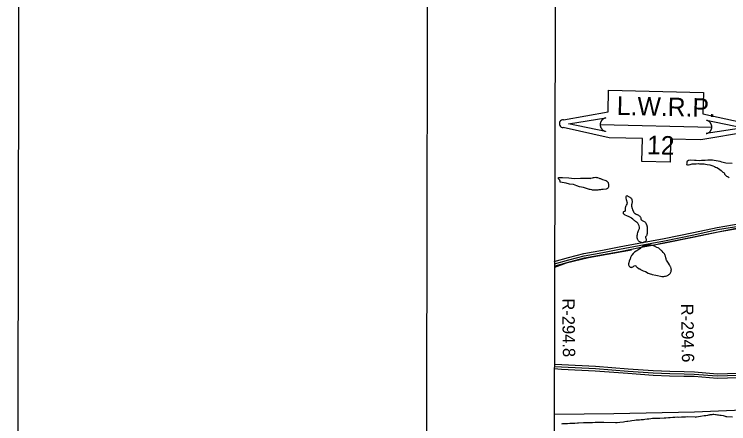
# Model space of a CAD drawing. Extents: x 3192986 to 3230865, y 867483 to 892886.
# Drawn here: x 3193570 to 3198376, y 880677 to 883432 of the extents above; entities that cross this region are included whole.
import ezdxf

# ---------------------------------------------------------------- set-up
doc = ezdxf.new("R2010")
doc.units = 0
for name, color, linetype in [('G-ANNO-NPLT', 7, 'Continuous'), ('V-ANNO-SYMB', 7, 'Continuous'), ('V-GRID-FRAM', 7, 'Continuous'), ('V-RIVR-RANG-IDEN', 7, 'Continuous'), ('V-ROAD-CNTR', 7, 'Continuous'), ('V-SITE-VEGE', 7, 'Continuous'), ('V-TOPO-SHOR', 7, 'Continuous'), ('V-TOPO-WATR-IDEN', 7, 'Continuous')]:
    doc.layers.add(name, color=color, linetype=linetype)

msp = doc.modelspace()

# ---------------------------------------------------------------- linework, layer by layer
at = {"layer": 'G-ANNO-NPLT'}
msp.add_lwpolyline([(3193569.6, 868136), (3230236.2, 868066.7), (3230281.9, 892233.3), (3193615.3, 892302.6)], close=True, dxfattribs=at)
at = {"layer": 'V-ANNO-SYMB'}
msp.add_lwpolyline([(3196320.9, 868755.9), (3229404.1, 868693.3), (3229447.4, 891609.8), (3196364.3, 891672.4), (3196320.9, 868755.9)], dxfattribs=at)
at = {"layer": 'V-GRID-FRAM'}
msp.add_lwpolyline([(3197186.7, 872920.9), (3197229, 891108.8)], dxfattribs=at)
at = {"layer": 'V-ROAD-CNTR'}
for points in [[(3197201.1, 881767.9), (3197297.4, 881794.4), (3197400.6, 881821.5), (3197527, 881844.1), (3197639.6, 881865.9), (3197770.6, 881891.1), (3197941.9, 881922.9), (3198139.7, 881963.1), (3198298.9, 881997.1), (3198452.7, 882023.6)], [(3197205.1, 881753.4), (3197301.3, 881779.9), (3197403.8, 881806.8), (3197529.8, 881829.4), (3197642.4, 881851.2), (3197773.4, 881876.4), (3197944.8, 881908.2), (3198142.7, 881948.4), (3198301.8, 881982.4), (3198456.9, 882009.1)], [(3197209.1, 881739), (3197305.2, 881765.5), (3197407, 881792.2), (3197532.5, 881814.6), (3197645.3, 881836.4), (3197776.2, 881861.7), (3197947.6, 881893.4), (3198145.8, 881933.7), (3198304.6, 881967.6), (3198461, 881994.6)], [(3198921.2, 881004.5), (3198905.7, 881010.4), (3198837.7, 881010.4), (3198724, 881007.7), (3198637.1, 881004.9), (3198571.8, 881015.2), (3198517.3, 881019.4), (3198456.9, 881015.6), (3198367.7, 881013.2), (3198298.5, 881010.8), (3198145.8, 881023.8), (3198076, 881025.1), (3197980, 881027.1), (3197868.7, 881032.1), (3197700.4, 881044), (3197480.4, 881060.6), (3197253.2, 881072), (3197204.4, 881075.1)], [(3198921.8, 880972.2), (3198900.2, 880980.4), (3198838, 880980.4), (3198724.8, 880977.7), (3198635.2, 880974.9), (3198568.3, 880985.3), (3198517.1, 880989.3), (3198458.2, 880985.7), (3198368.7, 880983.2), (3198297.7, 880980.8), (3198144.2, 880993.9), (3198075.4, 880995.1), (3197979, 880997.1), (3197867, 881002.2), (3197698.2, 881014.1), (3197478.5, 881030.6), (3197251.5, 881042), (3197202.5, 881045.2)], [(3198457.5, 881000.7), (3198368.2, 880998.2), (3198298.1, 880995.8), (3198145, 881008.8), (3198075.7, 881010.1), (3197979.5, 881012.1), (3197867.9, 881017.2), (3197699.3, 881029.1), (3197479.5, 881045.6), (3197252.4, 881057), (3197203.5, 881060.1)]]:
    msp.add_lwpolyline(points, dxfattribs=at)
at = {"layer": 'V-SITE-VEGE'}
for p, q in [((3198233, 880733.2), (3198236.6, 880734.9)), ((3198236.6, 880734.9), (3198241.9, 880737.1)), ((3198241.9, 880737.1), (3198246, 880737)), ((3198246, 880737), (3198252.5, 880738.1)), ((3198252.5, 880738.1), (3198257.2, 880738.6)), ((3198257.2, 880738.6), (3198266, 880739)), ((3198266, 880739), (3198270.8, 880740.1)), ((3198270.8, 880740.1), (3198276.6, 880740)), ((3198276.6, 880740), (3198286.6, 880738.6)), ((3198286.6, 880738.6), (3198292.5, 880737.9)), ((3198292.5, 880737.9), (3198301.3, 880737.1)), ((3198301.3, 880737.1), (3198308.3, 880735.8)), ((3198308.3, 880735.8), (3198317.1, 880733.9)), ((3197460.1, 880685.5), (3197477.2, 880686.4)), ((3197477.2, 880686.4), (3197489.5, 880686.1)), ((3197489.5, 880686.1), (3197507.2, 880686.4)), ((3197507.2, 880686.4), (3197519.5, 880686.1)), ((3197519.5, 880686.1), (3197537.2, 880687)), ((3197537.2, 880687), (3197615.3, 880685.4)), ((3197643, 880686), (3197669.5, 880688.5)), ((3197669.5, 880688.5), (3197678.4, 880690.6)), ((3197678.4, 880690.6), (3197691.3, 880692.7)), ((3197691.3, 880692.7), (3197698.4, 880694.4)), ((3197698.4, 880694.4), (3197712.6, 880696.4)), ((3197712.6, 880696.4), (3197724.4, 880698)), ((3197724.4, 880698), (3197742.1, 880701.1)), ((3197742.1, 880701.1), (3197753.8, 880702.7)), ((3197753.8, 880702.7), (3197776.2, 880703.4)), ((3197776.2, 880703.4), (3197788, 880704.3)), ((3197788, 880704.3), (3197793.8, 880704.2)), ((3197793.8, 880704.2), (3197802.1, 880705.8)), ((3197802.1, 880705.8), (3197810.9, 880706.2)), ((3197810.9, 880706.2), (3197828.1, 880709.4)), ((3197828.1, 880709.4), (3197838.1, 880709.8)), ((3197838.1, 880709.8), (3197853.4, 880711.3)), ((3197853.4, 880711.3), (3197862.8, 880712.9)), ((3197862.8, 880712.9), (3197876.3, 880713.2)), ((3197876.3, 880713.2), (3197885.2, 880714.2)), ((3197885.2, 880714.2), (3197896.3, 880714.5)), ((3197896.3, 880714.5), (3197912.8, 880714.2)), ((3197912.8, 880714.2), (3197941.6, 880715.4)), ((3197941.6, 880715.4), (3197952.8, 880717)), ((3197952.8, 880717), (3197971.1, 880717.8)), ((3197971.1, 880717.8), (3197982.9, 880719.3)), ((3197982.9, 880719.3), (3198001.1, 880720.1)), ((3198001.1, 880720.1), (3198012.9, 880721.6)), ((3198012.9, 880721.6), (3198031.1, 880721.9)), ((3198031.1, 880721.9), (3198041.7, 880721.7)), ((3198041.7, 880721.7), (3198057.6, 880723.1)), ((3198057.6, 880723.1), (3198067.6, 880722.9)), ((3198067.6, 880722.9), (3198081.1, 880723.2)), ((3198081.1, 880723.2), (3198085.2, 880723.2)), ((3198085.2, 880723.2), (3198096.4, 880724.1)), ((3198096.4, 880724.1), (3198150.5, 880723)), ((3198150.5, 880723), (3198154.6, 880721.8)), ((3198154.6, 880721.8), (3198158.7, 880722.9)), ((3198158.7, 880722.9), (3198174.1, 880726.1)), ((3198174.1, 880726.1), (3198187.6, 880728.2)), ((3198187.6, 880728.2), (3198210.6, 880731.3)), ((3198210.6, 880731.3), (3198222.4, 880731.6)), ((3198222.4, 880731.6), (3198233, 880733.2)), ((3198317.1, 880733.9), (3198325.3, 880733.1)), ((3198325.3, 880733.1), (3198338.2, 880731.1)), ((3198338.2, 880731.1), (3198345.2, 880729.2)), ((3198345.2, 880729.2), (3198353.4, 880727.3)), ((3198353.4, 880727.3), (3198358.1, 880726)), ((3198358.1, 880726), (3198363.4, 880724.7)), ((3198363.4, 880724.7), (3198401, 880724)), ((3197253.6, 880676.7), (3197260.1, 880677.1)), ((3197260.1, 880677.1), (3197269.5, 880678.1)), ((3197269.5, 880678.1), (3197285.4, 880677.8)), ((3197285.4, 880677.8), (3197291.9, 880678.3)), ((3197291.9, 880678.3), (3197306.6, 880679.8)), ((3197306.6, 880679.8), (3197316.6, 880680.1)), ((3197316.6, 880680.1), (3197330.7, 880681)), ((3197330.7, 880681), (3197340.7, 880680.8)), ((3197340.7, 880680.8), (3197358.9, 880681.7)), ((3197358.9, 880681.7), (3197366, 880681.5)), ((3197366, 880681.5), (3197400.1, 880683.8)), ((3197400.1, 880683.8), (3197414.3, 880684.1)), ((3197414.3, 880684.1), (3197426.6, 880685)), ((3197426.6, 880685), (3197434.3, 880685.5)), ((3197434.3, 880685.5), (3197448.4, 880685.8)), ((3197448.4, 880685.8), (3197460.1, 880685.5)), ((3197615.3, 880685.4), (3197625.9, 880685.8)), ((3197625.9, 880685.8), (3197643, 880686))]:
    msp.add_line(p, q, dxfattribs=at)
at = {"layer": 'V-TOPO-SHOR'}
for points in [[(3198398.5, 882428.2), (3198357.2, 882429.5), (3198347.6, 882431.5), (3198331.1, 882436.4), (3198318.9, 882440.3), (3198305.8, 882443.4), (3198277.9, 882448.6), (3198268.2, 882449.8), (3198252.4, 882450.3), (3198235.7, 882449.9), (3198217.2, 882448.7), (3198192.6, 882446.9), (3198177.6, 882446.4), (3198158.3, 882447), (3198146.9, 882448.3), (3198122.3, 882449), (3198104.7, 882446.9), (3198098.4, 882443.6), (3198094.8, 882441.1), (3198094.7, 882435.8), (3198093.6, 882428.8), (3198093.4, 882421.8), (3198098.6, 882419), (3198106.5, 882419.6), (3198117.1, 882421.1), (3198130.4, 882425), (3198135.7, 882425.8), (3198143.6, 882426.4), (3198156.8, 882426), (3198172.6, 882427.3), (3198180.5, 882426.1), (3198197.2, 882425.6), (3198210.3, 882424.3), (3198219.1, 882423.2), (3198230.4, 882420.2), (3198249.7, 882417.9), (3198268.8, 882412), (3198281, 882407.2)], [(3198281, 882407.2), (3198287, 882403.5), (3198295.7, 882400.6), (3198307.8, 882393.2), (3198316.4, 882387.7), (3198325, 882381.3), (3198337.8, 882370.3), (3198344.7, 882364), (3198347.2, 882359.5), (3198348.8, 882355.9), (3198353.1, 882351.4), (3198362.5, 882343.2), (3198367.7, 882340.4), (3198373.7, 882336.7), (3198379.8, 882333.9)], [(3197433.5, 882254.3), (3197398.9, 882266.5), (3197371.8, 882270.2), (3197354.2, 882278.2), (3197331.3, 882286.7), (3197305.9, 882289), (3197283.8, 882295.5), (3197255.8, 882299.9), (3197243.1, 882302.8), (3197242.4, 882309), (3197240.8, 882316.4), (3197230.5, 882324.9), (3197231.2, 882332.7), (3197258.2, 882333.5), (3197299.6, 882330.1), (3197337.6, 882326.9), (3197378.2, 882328.4), (3197410.7, 882328.7), (3197438.5, 882329.3)], [(3197438.5, 882329.3), (3197442.3, 882328.3), (3197445.8, 882327), (3197449.6, 882327.9), (3197460, 882331.9), (3197466.4, 882333.3), (3197471.4, 882334.1), (3197481.9, 882334.6), (3197486.6, 882334.2), (3197494.5, 882332.8), (3197504.3, 882329.9), (3197509.4, 882327.6), (3197513.1, 882326.3), (3197518.6, 882324), (3197526.6, 882320.9), (3197543.5, 882316.1), (3197549.2, 882313.7), (3197552.7, 882312), (3197555.2, 882310.3), (3197558.9, 882307.1), (3197561.5, 882303.8), (3197564.7, 882298.6), (3197565.8, 882295.4), (3197566.9, 882290.4), (3197567.4, 882286.8), (3197568.1, 882277.9), (3197566.8, 882270.2), (3197564.5, 882264.1), (3197561.4, 882259.7), (3197556.9, 882256.2), (3197551.7, 882254.4), (3197532.4, 882252.4), (3197528.1, 882252.6), (3197524.7, 882252.5), (3197519.9, 882252), (3197513.4, 882250.9), (3197502, 882249.4), (3197495.9, 882248.4), (3197487.3, 882247.7), (3197479.6, 882247.3), (3197465.2, 882248.2), (3197458.9, 882248.8), (3197455.1, 882249.3), (3197443.3, 882251.8), (3197440.2, 882252.1), (3197433.5, 882254.3)], [(3197759.9, 882030.5), (3197756.2, 882032.7), (3197749.3, 882037.4), (3197742.1, 882043.3), (3197738.4, 882046.7), (3197730.5, 882053.1), (3197722.8, 882058.9), (3197719.6, 882061.1), (3197712, 882065.4), (3197707.5, 882067.7), (3197690.9, 882074.5), (3197680.3, 882080), (3197674.5, 882083.6), (3197671.8, 882086), (3197669.4, 882089.2), (3197667.5, 882093.5), (3197667.5, 882097.4), (3197668.7, 882101.4), (3197670.9, 882104.6), (3197674.1, 882106.2), (3197677.1, 882106.5), (3197680.3, 882107.3), (3197681.6, 882110.6), (3197682, 882113.6), (3197682.5, 882127.2), (3197682.9, 882131.3), (3197683.4, 882135.3), (3197684.5, 882139.4), (3197685.9, 882142.9), (3197688, 882146.9), (3197692.6, 882154.2), (3197693.8, 882157.3), (3197694.4, 882160.3), (3197692.6, 882168.2), (3197689.9, 882178.8), (3197689.5, 882181.9), (3197686.3, 882199), (3197686.3, 882202.6), (3197687, 882206.6), (3197688.9, 882209.7), (3197691.5, 882211.5), (3197694.7, 882210.9), (3197698, 882208.7), (3197701.9, 882206.2), (3197707.3, 882202.2), (3197711.3, 882200.2), (3197716, 882197.4), (3197718.3, 882195.5), (3197721.2, 882191.4), (3197723.7, 882186.4), (3197725.6, 882181.4), (3197727.1, 882177.1), (3197727.3, 882172.5), (3197726.8, 882167.9), (3197726.2, 882164.9), (3197724.7, 882160.7), (3197723.7, 882156.8), (3197722.3, 882148.5), (3197723, 882138.9), (3197723.6, 882135.7), (3197724.6, 882131.4), (3197726.4, 882125.4), (3197729.8, 882115.8), (3197733, 882108), (3197735.7, 882102.2), (3197738.6, 882097.4), (3197742.1, 882093.6), (3197747.4, 882090), (3197752.8, 882087.2), (3197757.1, 882085.3), (3197761, 882083.9), (3197770, 882079.4), (3197774.4, 882076.5), (3197778.2, 882072.8), (3197780.6, 882069.3), (3197782.6, 882065.5), (3197784, 882061.8), (3197785.9, 882054.7), (3197788.4, 882049.6), (3197791.3, 882046), (3197793.6, 882043.8), (3197797.5, 882041.4), (3197802.6, 882039.3), (3197811, 882035.4), (3197813.8, 882032.9), (3197815.6, 882030.3), (3197817.8, 882025.9), (3197824.5, 882010.3), (3197825.5, 882007.3), (3197826.7, 882002.4), (3197827.4, 881996.4), (3197827.7, 881977.3), (3197828.1, 881970.2), (3197827.8, 881960.4), (3197827.3, 881955.4), (3197826.2, 881951), (3197824.9, 881945.5), (3197823.1, 881941.2), (3197818.2, 881936.3), (3197816.8, 881933.3), (3197817.5, 881928.1)], [(3197904.5, 881887.1), (3198428.1, 881993.5), (3198504.8, 882018.3), (3198581.6, 882049.4), (3198645.6, 882077.4), (3198702.9, 882070.5), (3198878.3, 882084.7), (3198907.1, 882097.2), (3198935.8, 882103.3), (3198986.8, 882106), (3199053.5, 882086.2), (3199025.5, 882214.7)], [(3197817.5, 881928.1), (3197818.6, 881925.2), (3197820.6, 881921.6), (3197821.8, 881918.4), (3197821.8, 881913.8), (3197820.8, 881908.9), (3197819, 881905), (3197816.3, 881902), (3197806.4, 881897.1), (3197801.8, 881895.4), (3197798.7, 881894.4), (3197793.9, 881894.4), (3197790.7, 881895), (3197786.9, 881896.1), (3197783.7, 881897.5), (3197778.5, 881900.3), (3197774.5, 881903.2), (3197771.9, 881905.4), (3197769.5, 881908), (3197767.3, 881910.8), (3197765.2, 881914.3), (3197763.4, 881917.5), (3197761.6, 881921.7), (3197760.6, 881927.5), (3197760.2, 881937.9), (3197760.8, 881943.1), (3197761.8, 881949.1), (3197762.5, 881954.8), (3197764.9, 881963.7), (3197767, 881970.2), (3197769.7, 881976.1), (3197772.4, 881980.7), (3197774.1, 881985.9), (3197775.6, 881991), (3197776.3, 881995.1), (3197776, 882000.1), (3197774.3, 882007.3), (3197772.3, 882013.7), (3197770.4, 882017.9), (3197768.1, 882021.9), (3197765.2, 882025.4), (3197763, 882027.7), (3197759.9, 882030.5)], [(3197722.4, 881844.3), (3197432, 881793), (3197281.8, 881756.2), (3197205.1, 881728.3)], [(3197837.3, 881879.2), (3197826.7, 881876.5), (3197823.4, 881876.6), (3197819.4, 881876.2), (3197816.1, 881875.5), (3197811.8, 881874.2), (3197801.9, 881872.4), (3197797.9, 881870.8), (3197793.4, 881867.9), (3197789.2, 881864.6), (3197786.1, 881861.9), (3197780.3, 881856.4), (3197771, 881849.5), (3197757.2, 881839.7), (3197754.1, 881837.3), (3197742.6, 881829.9), (3197739, 881826.8), (3197733.8, 881821.5), (3197725.5, 881811.8), (3197722.6, 881807.9), (3197717.7, 881799.3), (3197715.4, 881794.4), (3197714.5, 881791), (3197712.9, 881786), (3197706.6, 881769.3), (3197703.8, 881760), (3197702.4, 881752.5), (3197702.7, 881745.8), (3197703.8, 881741), (3197705.6, 881737.8), (3197710.1, 881732.6), (3197713.6, 881730.5), (3197719.6, 881728.9), (3197722.9, 881728.5), (3197727.1, 881729.1), (3197731.8, 881731.2), (3197736, 881734.9), (3197738.2, 881737.2), (3197741.3, 881739.8), (3197745.5, 881741.4), (3197750.9, 881738.6), (3197754.8, 881735.1), (3197758.5, 881731), (3197761.7, 881727.9), (3197764.6, 881725.4), (3197774.1, 881719.4), (3197777.6, 881717.7), (3197783.8, 881714.4), (3197801.7, 881705.9), (3197815.4, 881699.8), (3197835.4, 881690.1), (3197840.9, 881687.7), (3197847.7, 881685), (3197855.8, 881682.4), (3197861, 881681), (3197886.2, 881676.5), (3197898.1, 881674.1), (3197917.2, 881669.7), (3197927.4, 881668.3), (3197931.2, 881668.2), (3197936.8, 881668.1), (3197940.3, 881668.3), (3197947, 881669), (3197951.8, 881669.9), (3197960.4, 881672.1), (3197968.9, 881676.5), (3197973.9, 881679.6), (3197977.1, 881682.3), (3197981.9, 881687.7), (3197984.4, 881691.2), (3197988.5, 881699.9), (3197990.1, 881706.7), (3197990.4, 881713.7), (3197990.1, 881717), (3197989, 881721.8), (3197986.2, 881729.5), (3197985.1, 881732.3), (3197982.6, 881737.2), (3197980.5, 881740.8), (3197977.1, 881745.9), (3197970.7, 881756.6), (3197961.6, 881771.2), (3197958.7, 881777.3), (3197956.6, 881782), (3197955.5, 881785.2), (3197953.6, 881793.2), (3197951.8, 881803.5), (3197949.8, 881809.3), (3197946.4, 881815.2), (3197944, 881818.9), (3197935.2, 881829.8), (3197928.6, 881837.4), (3197924.4, 881841.8), (3197920.5, 881845.4), (3197913.9, 881851.1), (3197911.1, 881853.1), (3197905.3, 881856.8), (3197900.8, 881859.4), (3197893.8, 881863), (3197876.2, 881870.8), (3197871, 881872.9)], [(3197871, 881872.9), (3197860.7, 881876.4), (3197855.7, 881877.5), (3197849.1, 881878.3), (3197842.6, 881878.6), (3197837.3, 881879.2)], [(3200534.2, 880915), (3200285.3, 880882.4), (3200119.5, 880872.9), (3199682.9, 880861.2), (3199446.9, 880849.2), (3199329, 880845.6), (3199178.9, 880815.2), (3199064.1, 880800.4), (3198995.5, 880794.7), (3198740.4, 880778), (3198145.9, 880755.2), (3197602.5, 880742.9), (3197204.9, 880739.5)]]:
    msp.add_lwpolyline(points, dxfattribs=at)
at = {"layer": 'V-TOPO-WATR-IDEN'}
msp.add_line((3197511.6, 882689.8), (3198262.6, 882672.6), dxfattribs=at)
for points in [[(3197264.3, 882721.9), (3197565, 882775.8), (3197568.3, 882920.5), (3198206.6, 882905.9), (3198203.3, 882761.2), (3198511.1, 882693.5)], [(3198509.9, 882640.5), (3198188.8, 882587.1), (3197985.4, 882591.7), (3197981.9, 882436.4), (3197792.8, 882440.7), (3197796.4, 882596), (3197571.6, 882601.2), (3197263.1, 882668.9)]]:
    msp.add_lwpolyline(points, dxfattribs=at)
for points in [[(3197548.1, 882643.9), (3197299.3, 882694.6), (3197550.1, 882733.9), (3197545.7, 882732.9), (3197541.5, 882731.6), (3197539.8, 882731), (3197538.4, 882730.3), (3197536.7, 882729.5), (3197535, 882728.7), (3197533.7, 882727.9), (3197531.8, 882726.7), (3197529.9, 882725.3), (3197528.9, 882724.6), (3197527.6, 882723.5), (3197526, 882722), (3197524.7, 882720.8), (3197523.5, 882719.5), (3197522.7, 882718.5), (3197521.8, 882717.5), (3197520.8, 882716.2), (3197519.9, 882715), (3197519.1, 882713.8), (3197518.4, 882712.7), (3197517.5, 882711.1), (3197516.6, 882709.6), (3197516, 882708.3), (3197515.3, 882706.8), (3197514.8, 882705.5), (3197514.3, 882704.3), (3197514, 882703.4), (3197513.6, 882702), (3197513.1, 882700.5), (3197512.8, 882699), (3197512.5, 882697.6), (3197512.2, 882696.2), (3197512, 882694.7), (3197511.8, 882693.5), (3197511.7, 882691.7), (3197511.6, 882689.8), (3197511.6, 882689.1), (3197511.6, 882688.2), (3197511.6, 882687.1), (3197511.7, 882686), (3197511.7, 882685), (3197511.8, 882684), (3197512, 882682.8), (3197512.1, 882682), (3197512.3, 882680.8), (3197512.5, 882679.7), (3197512.7, 882678.9), (3197513.1, 882676.9), (3197513.4, 882675.9), (3197513.6, 882675.2), (3197514, 882674), (3197514.4, 882673), (3197514.8, 882671.9), (3197515.3, 882670.7), (3197515.8, 882669.5), (3197516.2, 882668.6), (3197516.6, 882667.9), (3197517.1, 882666.9), (3197517.6, 882666), (3197518.2, 882665), (3197518.9, 882663.9), (3197519.6, 882662.9), (3197520.5, 882661.6), (3197521.1, 882660.8), (3197521.9, 882659.8), (3197522.7, 882658.9), (3197523.3, 882658.1), (3197524, 882657.4), (3197525.1, 882656.2), (3197525.2, 882656.2), (3197525.8, 882655.5), (3197526.3, 882655.1), (3197527.1, 882654.4), (3197528.1, 882653.5), (3197528.9, 882652.9), (3197529.6, 882652.3), (3197530.5, 882651.6), (3197531.5, 882651), (3197532.2, 882650.5), (3197533, 882650), (3197534.3, 882649.2), (3197535, 882648.8), (3197535.6, 882648.4), (3197536.2, 882648.1), (3197536.9, 882647.8), (3197537.7, 882647.4), (3197538.6, 882647), (3197539.5, 882646.6), (3197540.4, 882646.2), (3197541.6, 882645.8), (3197542.3, 882645.5), (3197543.4, 882645.1), (3197544.7, 882644.7), (3197545.7, 882644.5), (3197546.5, 882644.3), (3197547.2, 882644.1), (3197547.7, 882644)], [(3198226.1, 882718.5), (3198475, 882667.8), (3198224.1, 882628.5), (3198228.6, 882629.5), (3198232.8, 882630.8), (3198234.4, 882631.4), (3198235.9, 882632.1), (3198237.6, 882632.9), (3198239.2, 882633.7), (3198240.5, 882634.5), (3198242.4, 882635.7), (3198244.3, 882637.1), (3198245.3, 882637.8), (3198246.6, 882638.9), (3198248.3, 882640.4), (3198249.5, 882641.6), (3198250.8, 882642.9), (3198251.6, 882643.9), (3198252.4, 882644.9), (3198253.4, 882646.2), (3198254.3, 882647.4), (3198255.2, 882648.6), (3198255.8, 882649.7), (3198256.8, 882651.3), (3198257.6, 882652.8), (3198258.2, 882654.1), (3198258.9, 882655.6), (3198259.4, 882656.9), (3198259.9, 882658.1), (3198260.2, 882659), (3198260.7, 882660.4), (3198261.1, 882661.9), (3198261.4, 882663.4), (3198261.8, 882664.8), (3198262, 882666.2), (3198262.2, 882667.7), (3198262.4, 882668.9), (3198262.5, 882670.7), (3198262.6, 882672.6), (3198262.6, 882673.3), (3198262.6, 882674.2), (3198262.6, 882675.3), (3198262.5, 882676.4), (3198262.5, 882677.4), (3198262.4, 882678.4), (3198262.2, 882679.6), (3198262.1, 882680.4), (3198261.9, 882681.6), (3198261.7, 882682.7), (3198261.6, 882683.5), (3198261.1, 882685.5), (3198260.8, 882686.5), (3198260.6, 882687.2), (3198260.2, 882688.4), (3198259.8, 882689.4), (3198259.4, 882690.5), (3198258.9, 882691.7), (3198258.4, 882692.9), (3198258, 882693.8), (3198257.6, 882694.5), (3198257.1, 882695.5), (3198256.6, 882696.4), (3198256, 882697.4), (3198255.3, 882698.5), (3198254.7, 882699.5), (3198253.8, 882700.8), (3198253.1, 882701.6), (3198252.3, 882702.6), (3198251.6, 882703.5), (3198250.9, 882704.3), (3198250.2, 882705), (3198249.1, 882706.2), (3198249.1, 882706.2), (3198248.4, 882706.9), (3198247.9, 882707.3), (3198247.1, 882708), (3198246.1, 882708.9), (3198245.3, 882709.5), (3198244.6, 882710.1), (3198243.7, 882710.8), (3198242.7, 882711.4), (3198242.1, 882711.9), (3198241.2, 882712.5), (3198239.9, 882713.2), (3198239.2, 882713.6), (3198238.6, 882714), (3198238, 882714.3), (3198237.4, 882714.6), (3198236.5, 882715), (3198235.6, 882715.4), (3198234.7, 882715.8), (3198233.8, 882716.2), (3198232.6, 882716.6), (3198231.9, 882716.9), (3198230.8, 882717.3), (3198229.5, 882717.7), (3198228.5, 882717.9), (3198227.7, 882718.1), (3198227, 882718.3), (3198226.5, 882718.4)]]:
    msp.add_lwpolyline(points, close=True, dxfattribs=at)
msp.add_arc((3197263.7, 882695.4), 26.5, 88.6951, 268.6951, dxfattribs=at)

# ---------------------------------------------------------------- texts
at = {"layer": 'V-RIVR-RANG-IDEN'}
for s, rotation, p in [('R-294.8', 270.7577, (3197255.7, 881519.2)), ('R-294.6', 270.9666, (3198055.5, 881483.6))]:
    msp.add_text(s, height=83, rotation=rotation, dxfattribs=at).set_placement(p)
at = {"layer": 'V-TOPO-WATR-IDEN'}
for s, rotation, p in [('L.W.R.P.', 358.695, (3197622.3, 882754.8)), ('12', 358.6951, (3197825.6, 882490.6))]:
    msp.add_text(s, height=124.5, rotation=rotation, dxfattribs=at).set_placement(p)

doc.saveas('drawing.dxf')
